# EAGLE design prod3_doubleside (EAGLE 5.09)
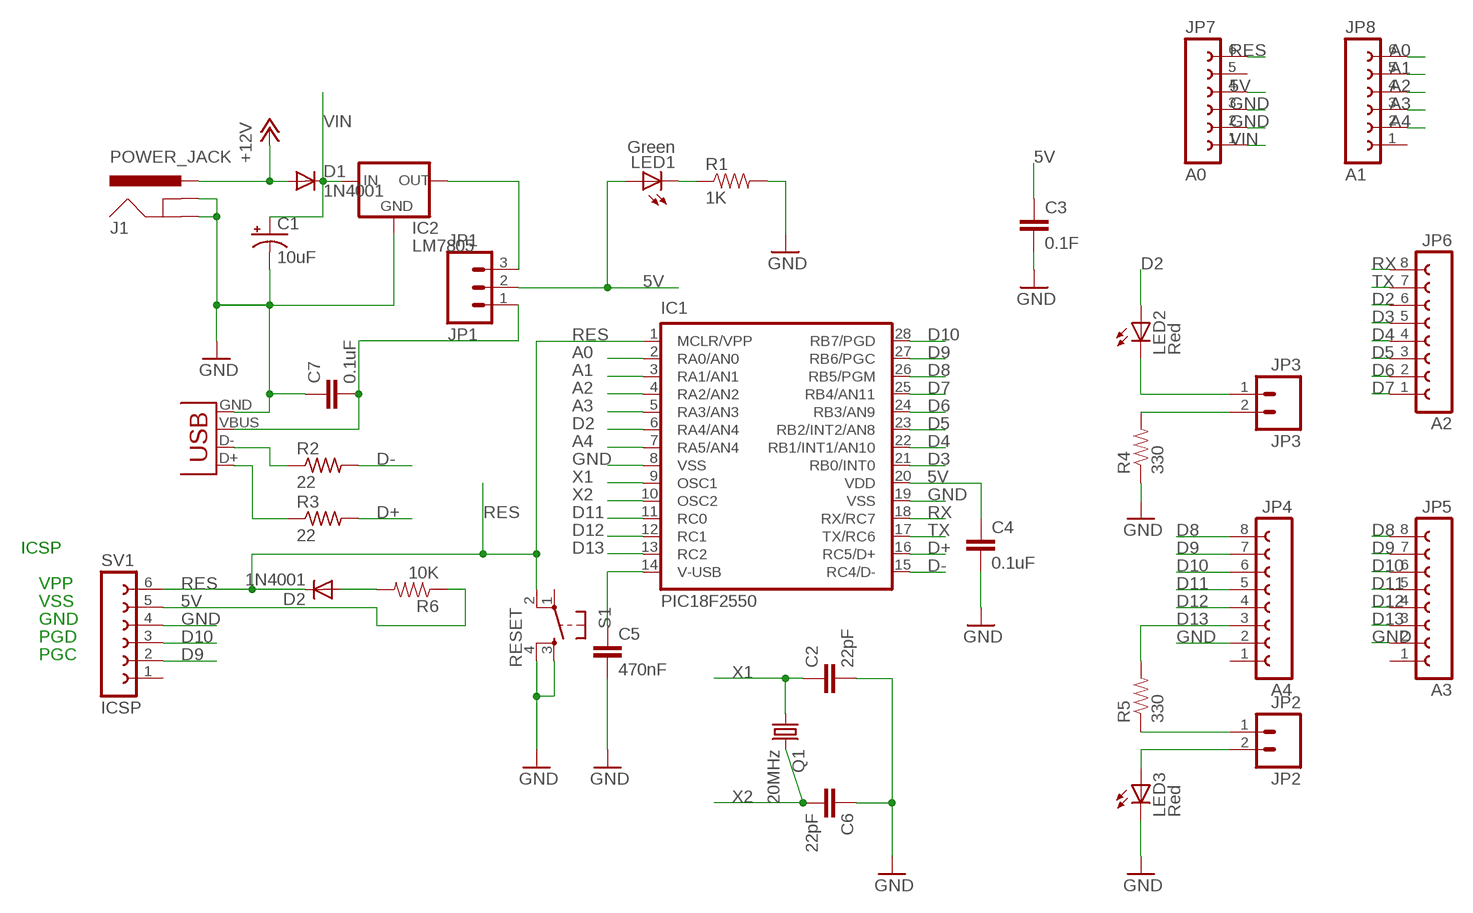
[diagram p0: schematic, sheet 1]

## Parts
C1  10uF  CAP_POLPTH2  [CPOL-RADIAL-10UF-25V]
C2  22pF  CAPPTH  [CAP-PTH-SMALL]
C3  0.1F  CAPPTH1  [CAP-PTH-5MM]
C4  0.1uF  CAPPTH  [CAP-PTH-SMALL]
C5  470nF  CAPPTH1  [CAP-PTH-5MM]
C6  22pF  CAPPTH  [CAP-PTH-SMALL]
C7  0.1uF  CAPPTH  [CAP-PTH-SMALL]
D1  1N4001  DIODEPTH  [DIODE-1N4001]
D2  1N4001  DIODEPTH  [DIODE-1N4001]
IC1  PIC18F2550  [DIL28-3]
IC2  LM7805  V_REG_78XXSIDE  [78XXL]
J1  POWER_JACK  POWER_JACKPTH  [POWER_JACK_PTH]
JP1  JP1  M03PTH  [1X03]
JP2  JP2  M02PTH  [1X02]
JP3  JP3  M02PTH  [1X02]
JP4  A4  FE08-1  [FE08]
JP5  A3  FE08-1  [FE08]
JP6  A2  FE08-1  [FE08]
JP7  A0  FE06-1  [FE06]
JP8  A1  FE06-1  [FE06]
LED1  Green  LED3MM  [LED3MM]
LED2  Red  LED3MM  [LED3MM]
LED3  Red  LED3MM  [LED3MM]
Q1  20MHz  CRYSTALHC49US  [HC49US]
R1  1K  RESISTORPTH1  [AXIAL-0.3]
R2  22  R-US_0207/15  [0207/15]
R3  22  R-US_0207/15  [0207/15]
R4  330  RESISTORPTH1  [AXIAL-0.3]
R5  330  RESISTORPTH1  [AXIAL-0.3]
R6  10K  RESISTORPTH1  [AXIAL-0.3]
S1  RESET  TAC_SWITCHPTH  [TACTILE-PTH]
SV1  ICSP  FE06-1  [FE06]
X1  USBPTH  [USB-B-PTH]

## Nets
5V: C3.1 C4.1 IC1.20(VDD) JP1.2 JP7.4 LED1.A R6.P$1 SV1.5
+12V: D1.A J1.PWR
A0: IC1.2(RA0/AN0) JP8.6
A1: IC1.3(RA1/AN1) JP8.5
A2: IC1.4(RA2/AN2) JP8.4
A3: IC1.5(RA3/AN3) JP8.3
A4: IC1.7(RA5/AN4) JP8.2
D2: IC1.6(RA4/AN4) JP6.6 LED2.A
D3: IC1.21(RB0/INT0) JP6.5
D4: IC1.22(RB1/INT1/AN10) JP6.4
D5: IC1.23(RB2/INT2/AN8) JP6.3
D6: IC1.24(RB3/AN9) JP6.2
D7: IC1.25(RB4/AN11) JP6.1
D8: IC1.26(RB5/PGM) JP4.8 JP5.8
D9: IC1.27(RB6/PGC) JP4.7 JP5.7 SV1.2
D10: IC1.28(RB7/PGD) JP4.6 JP5.6 SV1.3
D11: IC1.11(RC0) JP4.5 JP5.5
D12: IC1.12(RC1) JP4.4 JP5.4
D13: IC1.13(RC2) JP4.3 JP5.3 R5.P$2
D+: IC1.16(RC5/D+) R3.2
D-: IC1.15(RC4/D-) R2.2
GND: C1.2(-) C2.2 C3.2 C4.2 C5.2 C6.1 C7.1 IC1.8(VSS) IC1.19(VSS) IC2.GND J1.GND J1.GNDBREAK JP4.2 JP5.2 JP7.2 JP7.3 LED3.K(C) R1.P$2 R4.P$1 S1.3 S1.4 SV1.4 X1.GND
N$1: D2.A R6.P$2
N$2: LED1.K(C) R1.P$1
N$3: JP3.2 R4.P$2
N$4: C7.2 JP1.1 X1.VBUS
N$5: R2.1 X1.D-
N$6: R3.1 X1.D+
N$7: JP3.1 LED2.K(C)
N$8: JP2.1 R5.P$1
N$10: JP2.2 LED3.A
N$11: IC2.OUT JP1.3
N$15: C5.1 IC1.14(V-USB)
RES: D2.C IC1.1(MCLR/VPP) JP7.6 S1.2 SV1.6
RX: IC1.18(RX/RC7) JP6.8
TX: IC1.17(TX/RC6) JP6.7
VIN: C1.1(+) D1.C IC2.IN JP7.1
X1: C2.1 IC1.9(OSC1) Q1.1
X2: C6.2 IC1.10(OSC2) Q1.2
Unconnected: JP4.1 JP5.1 JP7.5 JP8.1 S1.1 SV1.1

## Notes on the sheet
- ICSP
- VPP
- VSS
- GND
- PGD
- PGC

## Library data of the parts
C1 = SparkFun:CAP_POL: Capacitor Polarized
C2-C7 = SparkFun:CAP: Capacitor
D1 D2 = SparkFun:DIODE: Diode
IC1 = SparkFun:PIC18F2550
IC2 = SparkFun:V_REG_78XX: Voltage Regulator Standard 7805 5V regulator. IGO (Input Ground Output). Spark Fun Electronics SKU : COM-00107
J1 = SparkFun:POWER_JACK: Power Jack This is the standard 5.5mm barrel jack for power. The PTH is the most common, proven, reliable, footprint. All others are experimental. The Slot footprint only works if the mill layer is transmitted to the PCB fab house so be warned. Spark Fun Electronics SKU : PRT-00119. Mating wall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
JP1 = SparkFun:M03: Header 3 Standard 3-pin 0.1" header. Use with straight break away headers (SKU : PRT-00116), right angle break away headers (PRT-00553), swiss pins (PRT-00743), machine pins (PRT-00117), and female headers (PRT-00115). Molex polarized connector foot print use with SKU : PRT-08232 with associated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
JP2 JP3 = SparkFun:M02: Header 2
JP4-JP6 = con-lsta:FE08-1: FEMALE HEADER
JP7 JP8 SV1 = con-lsta:FE06-1: FEMALE HEADER
LED1-LED3 = SparkFun:LED: LEDs
Q1 = SparkFun:CRYSTAL: Crystals
R1 R4-R6 = SparkFun:RESISTOR: Resistor
R2 R3 = rcl:R-US_: RESISTOR, American symbol
S1 = SparkFun:TAC_SWITCH: Momentary Switch Button commonly used for reset or general input. Spark Fun Electronics SKU : COM-00097
X1 = SparkFun:USB: USB Connectors USB-B-PTH is fully proven SKU : PRT-00139 USB-miniB is fully proven SKU : PRT-00587 USB-A-PCB is untested. USB-A-H is throughly reviewed, but untested. Spark Fun Electronics SKU : PRT-00437 USB-B-SMT is throughly reviewed, but untested. Needs silkscreen touching up. USB-A-S has not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

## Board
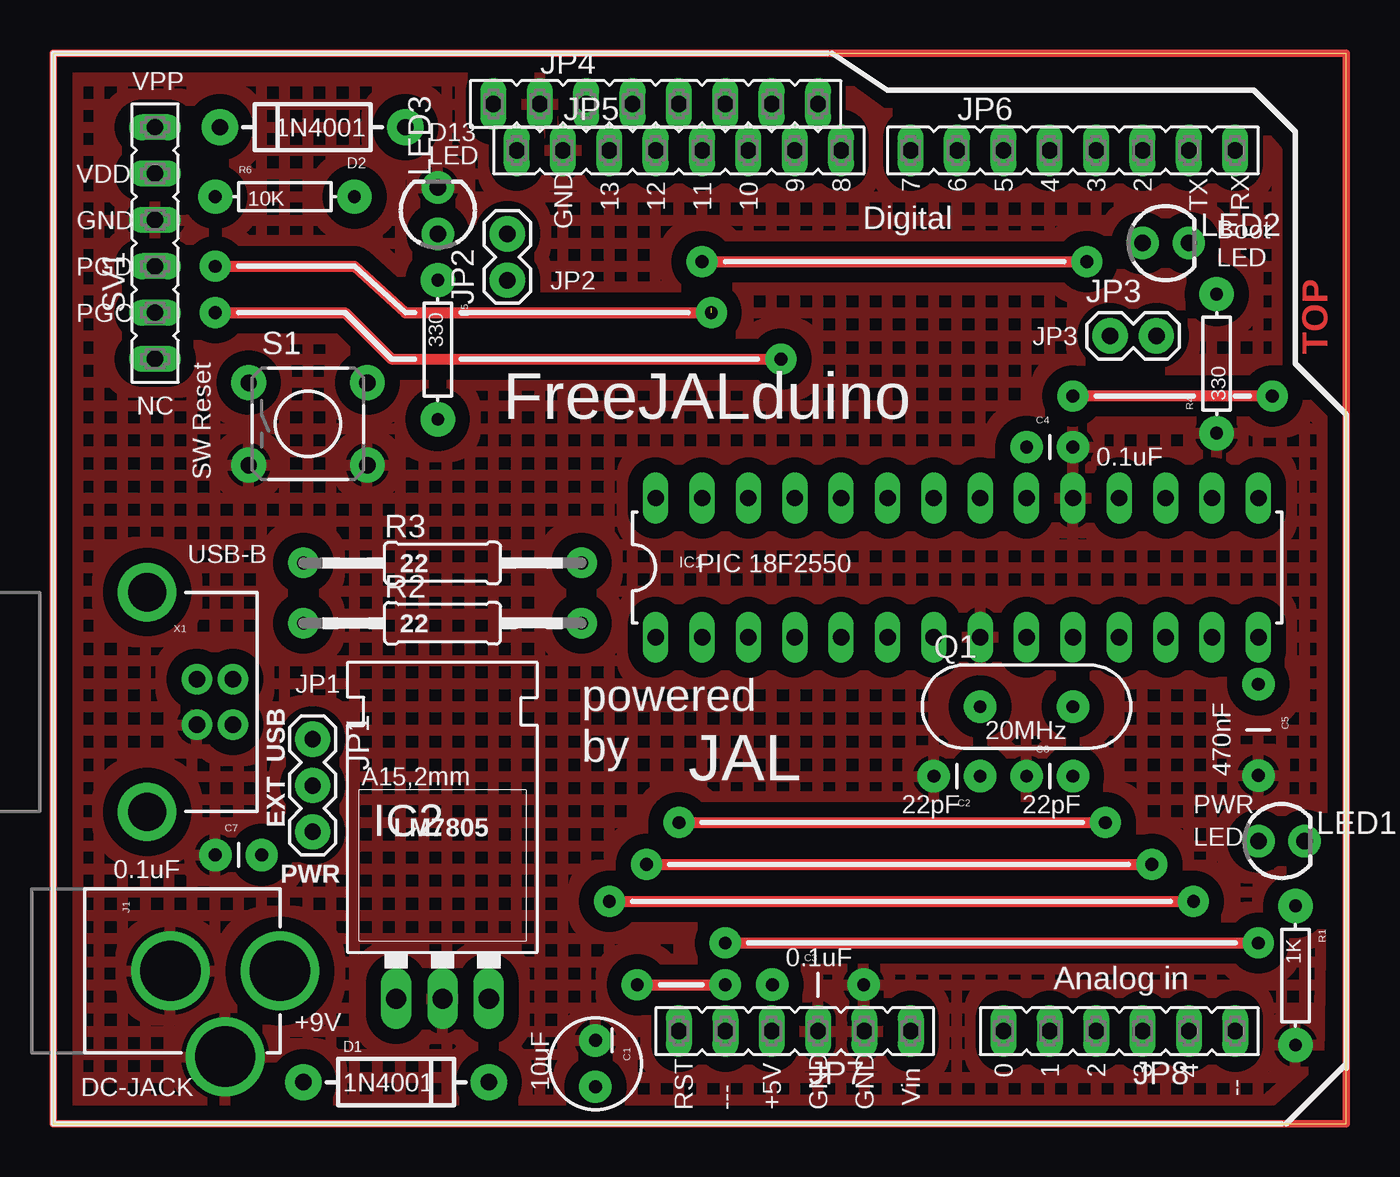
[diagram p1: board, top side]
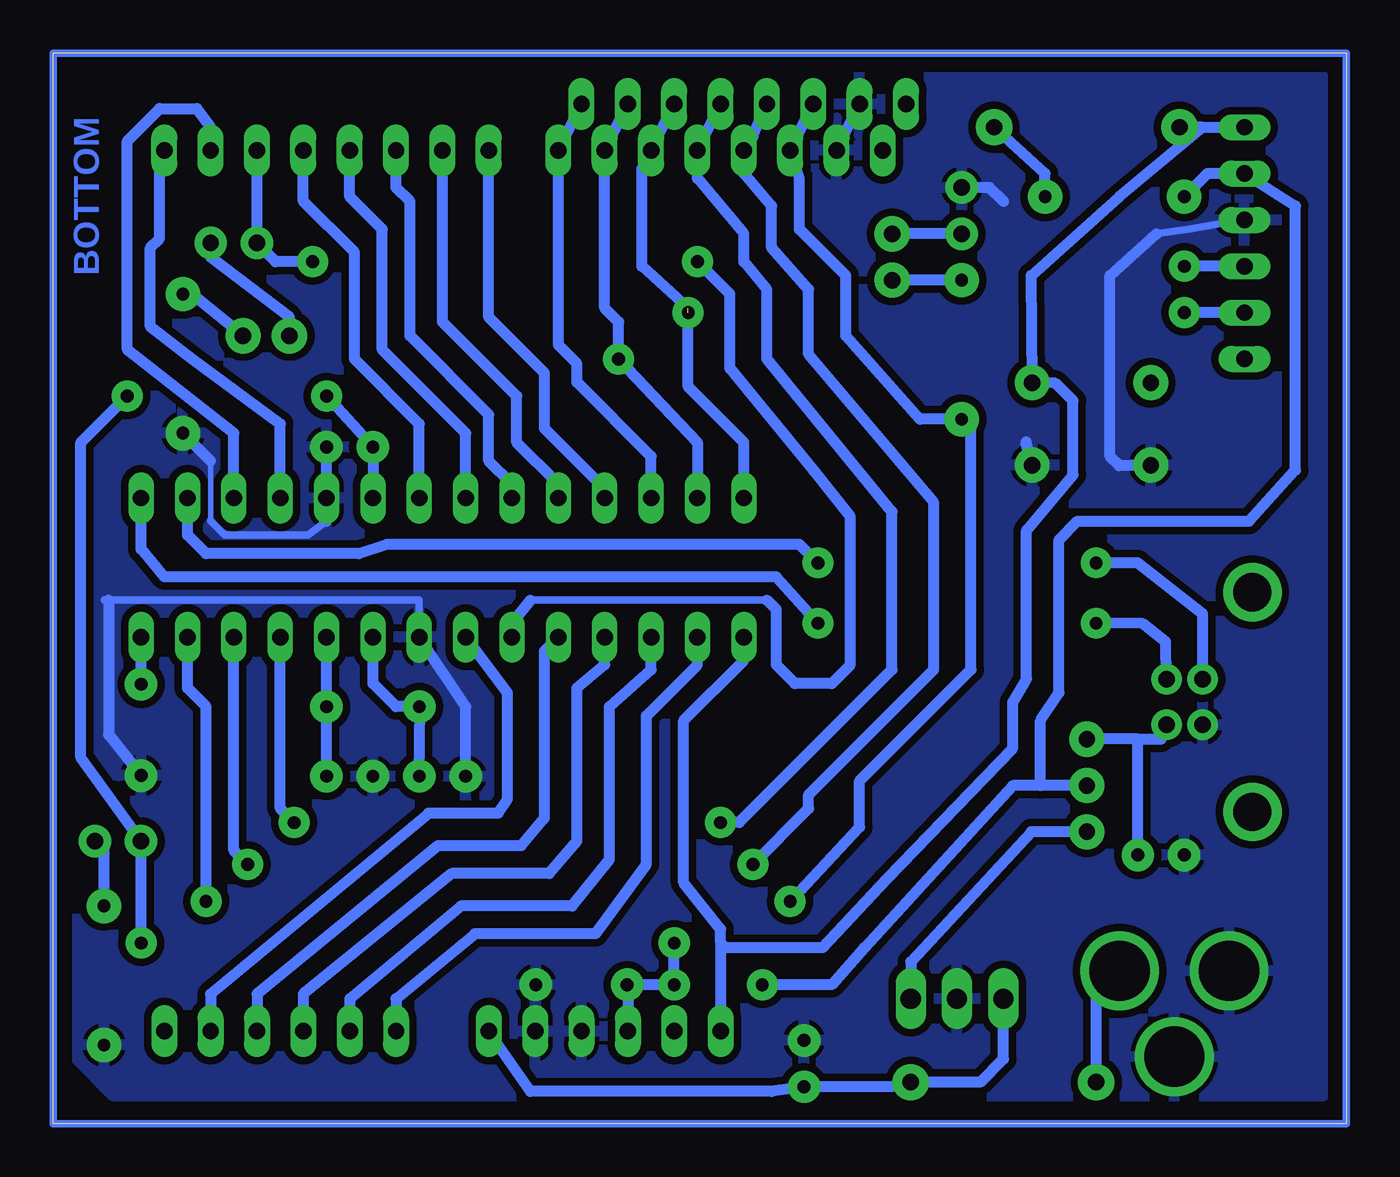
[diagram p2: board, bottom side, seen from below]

Size 70.87 x 58.67 mm. Coordinates in mm from the lower left corner, seen from the top.
Outline: 0,0 70.87,0 70.87,58.67 0,58.67 0,0
Copper layers (1*16): Top 0.035mm / dielectric 1.5mm / Bottom 0.035mm
Design rules "10mils": minimum track width 10mil, minimum drill 24mil, track to track 10mil, track to pad 10mil, pad to pad 10mil, via to via 10mil, smd to smd 10mil, copper to edge 40mil, drill to drill 10mil, minimum pad ring 10mil, minimum via ring 8mil, stop-mask expansion 0mil, vias tented up to drill 0mil, thermal gap 10mil

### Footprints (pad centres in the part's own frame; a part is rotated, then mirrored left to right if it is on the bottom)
CPOL-RADIAL-10UF-25V = drill 0.7 pad 1.778 round: 1 1.27,0; 2 -1.27,0
CAP-PTH-SMALL = drill 0.7 pad 1.778 round: 1 0,0; 2 2.54,0
CAP-PTH-5MM = drill 0.7 pad 1.778 round: 1 -2.5,0; 2 2.5,0
DIODE-1N4001 = drill 0.9 pad 1.981 round: A -5.08,0; C 5.08,0
DIL28-3 = drill 0.9 pad 1.27 long: 1 -16.51,-3.81; 2 -13.97,-3.81; 3 -11.43,-3.81; 4 -8.89,-3.81; 5 -6.35,-3.81; 6 -3.81,-3.81; 7 -1.27,-3.81; 8 1.27,-3.81; 9 3.81,-3.81; 10 6.35,-3.81; 11 8.89,-3.81; 12 11.43,-3.81; 13 13.97,-3.81; 14 16.51,-3.81; 15 16.51,3.81; 16 13.97,3.81; 17 11.43,3.81; 18 8.89,3.81; 19 6.35,3.81; 20 3.81,3.81; 21 1.27,3.81; 22 -1.27,3.81; 23 -3.81,3.81; 24 -6.35,3.81; 25 -8.89,3.81; 26 -11.43,3.81; 27 -13.97,3.81; 28 -16.51,3.81
78XXL = drill 1.1 pad 1.676 long: GND 0,-3.81; IN -2.54,-3.81; OUT 2.54,-3.81
POWER_JACK_PTH = drill 3.3 pad 4 round: GND 0,7.7; GNDBREAK 4.7,10.7; PWR 0,13.7
1X03 = drill 0.9 pad 1.93 round: 1 0,0; 2 2.54,0; 3 5.08,0
1X02 = drill 0.9 pad 1.93 round: 1 0,0; 2 2.54,0
FE08 = drill 0.9 pad 1.422 long: 1 -8.89,0; 2 -6.35,0; 3 -3.81,0; 4 -1.27,0; 5 1.27,0; 6 3.81,0; 7 6.35,0; 8 8.89,0
FE06 = drill 0.9 pad 1.422 long: 1 -6.35,0; 2 -3.81,0; 3 -1.27,0; 4 1.27,0; 5 3.81,0; 6 6.35,0
LED3MM = drill 0.9 pad 1.778 round: A -1.27,0; K 1.27,0
HC49US = drill 0.7 pad 1.778 round: 1 -2.54,0; 2 2.54,0
AXIAL-0.3 = drill 0.7 pad 1.88 round: P$1 -3.81,0; P$2 3.81,0
0207/15 = drill 0.7 pad 1.676 round: 1 -7.62,0; 2 7.62,0
TACTILE-PTH = drill 0.9 pad 1.9 round: 1 -3.251,2.261; 2 3.251,2.261; 3 -3.251,-2.261; 4 3.251,-2.261
USB-B-PTH = drill 0.9 pad 1.676 round: D+ 0,1.25; D- 1.981,1.25; GND 0,-1.25; VBUS 1.981,-1.25 | drill 2.1 pad 3.2 round: P$1 -2.718,-6.02; P$2 -2.718,6.02

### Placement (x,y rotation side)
C1  29.72,3.3 270 top
C2  50.8,19.05 180 top
C3  41.91,7.62 0 top
C4  53.34,37.08 0 top
C5  66.04,21.59 270 top
C6  53.34,19.05 0 top
C7  8.89,14.73 0 top
D1  18.8,2.29 0 top
D2  14.22,54.61 180 top
IC1  49.53,30.48 0 top
IC2  21.34,10.67 0 top
J1  -1.27,8.38 270 top
JP1  14.22,21.08 270 top
JP2  24.89,46.23 90 top
JP3  57.91,43.18 0 top
JP4  33.02,55.88 0 top
JP5  34.29,53.34 0 top
JP6  55.88,53.34 0 top
JP7  40.64,5.08 180 top
JP8  58.42,5.08 180 top
LED1  67.31,15.49 0 top
LED2  60.96,48.26 0 top
LED3  21.08,50.04 90 top
Q1  53.34,22.86 0 top
R1  68.07,8.13 270 top
R2  21.34,27.43 0 top
R3  21.34,30.73 0 top
R4  63.75,41.66 90 top
R5  21.08,42.42 270 top
R6  12.7,50.8 0 top
S1  13.97,38.35 0 top
SV1  5.59,48.26 90 top
X1  7.87,23.11 0 top

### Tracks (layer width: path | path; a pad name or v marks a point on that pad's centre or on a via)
5V  (via drill 0.7 pad 1.7)
  Top 0.61: C3.1 39.62,7.62 | v32,7.62 v36.83,7.62 | v36.83,9.91 v66.04,9.91 | v66.8,39.88 v55.88,39.88
  Bottom 0.61: R6.P$1 7.62,52.07 SV1.5 2.79,50.29 2.79,35.81 5.33,33.02 14.73,33.02 15.75,32 15.75,23.62 16.76,22.1 16.76,18.54 | IC1.20 C4.1 v55.88,39.88 | JP7.4 39.37,7.58 C3.1 v36.83,7.62 v36.83,9.91 | JP1.2 16.76,18.54 | 16.76,18.54 18.29,18.54 26.42,9.65 28.19,7.62 v32,7.62 | v66.04,9.91 LED1.A 69.34,20.07 69.34,37.34 v66.8,39.88
+12V
  Bottom 0.61: J1.PWR 12.43,8.4 13.72,7.11 D1.A
A0
  Bottom 0.61: IC1.2 35.56,25.15 38.35,22.35 38.35,14.22 41.15,10.41 47.75,10.41 52.07,6.86 JP8.6
A1
  Bottom 0.61: IC1.3 38.1,24.89 40.39,22.86 40.39,14.48 42.42,11.94 48.51,11.94 54.61,6.86 JP8.5
A2
  Bottom 0.61: IC1.4 40.64,25.15 42.16,23.88 42.16,15.49 43.69,13.72 49.02,13.72 57.15,7.11 JP8.4
A3
  Bottom 0.61: JP8.3 59.69,7.11 49.78,15.24 45.21,15.24 43.94,16.76 43.94,25.91 IC1.5
A4
  Bottom 0.61: IC1.7 45.97,23.62 45.97,17.78 46.48,17.02 50.29,17.02 62.23,7.11 JP8.2
D2  (via drill 0.7 pad 1.7)
  Top 0.61: v35.56,47.24 v56.64,47.24
  Bottom 0.406: 31.75,28.7 44.7,28.7
  Bottom 0.61: IC1.6 45.72,27.43 44.7,28.7 | 31.75,28.7 31.24,28.19 31.24,25.15 30.23,24.13 28.19,24.13 27.18,25.15 27.18,33.27 29.21,35.81 33.78,41.4 33.78,45.47 v35.56,47.24 | JP6.6 LED2.A 58.67,47.24 v56.64,47.24
D3
  Bottom 0.61: IC1.21 50.8,38.35 54.36,41.91 54.36,47.75 57.15,50.55 JP6.5
D4
  Bottom 0.61: IC1.22 48.26,37.85 52.83,42.42 52.83,49.02 54.61,50.8 JP6.4
D5
  Bottom 0.61: IC1.23 45.72,35.05 46.99,36.32 46.99,38.86 51.31,43.18 51.31,50.55 52.07,51.31 JP6.3
D6
  Bottom 0.61: IC1.24 43.18,35.05 45.47,37.34 45.47,39.88 49.53,43.94 JP6.2
D7
  Bottom 0.61: IC1.25 40.64,34.8 43.94,38.1 43.94,41.15 46.99,44.2 JP6.1
D8
  Bottom 0.61: IC1.26 38.1,36.58 42.16,40.64 42.16,41.66 43.18,42.67 JP5.8 JP4.8
D9  (via drill 0.7 pad 1.7)
  Top 0.61: v8.89,44.45 16,44.45 18.54,41.91 v39.88,41.91
  Bottom 0.61: IC1.27 35.56,37.34 v39.88,41.91 39.88,43.94 40.64,44.7 JP5.7 JP4.7 | SV1.2 v8.89,44.45
D10  (via drill 0.7 pad 1.7)  (1 unrouted)
  Top 0.61: v8.89,46.99 16.51,46.99 19.3,44.45 v36.07,44.45
  Bottom 0.61: IC1.28 33.02,37.34 36.07,40.39 36.07,44.7 38.61,46.99 38.61,52.32 JP5.6 JP4.6 | SV1.3 v8.89,46.99
D11  (via drill 0.7 pad 1.7)
  Top 0.61: v34.29,16.51 v57.66,16.51
  Bottom 0.61: IC1.11 58.42,17.27 v57.66,16.51 | v34.29,16.51 33.27,16.51 24.89,24.89 24.89,33.53 31.75,41.91 31.75,45.72 33.02,47.24 33.02,48.77 35.56,51.82 JP5.5 JP4.5
D12  (via drill 0.7 pad 1.7)
  Top 0.61: v32.51,14.22 v60.2,14.22
  Bottom 0.61: 32.63,53.93 JP5.4 33.02,52.07 31.5,50.29 31.5,48.01 29.46,45.72 29.46,42.16 22.61,34.04 22.61,24.89 29.46,18.03 29.46,17.27 v32.51,14.22 | 32.63,53.93 32.51,54.1 | IC1.12 60.96,14.99 v60.2,14.22 | 32.63,53.93 JP4.4
D13  (via drill 0.7 pad 1.7)
  Top 0.61: v30.48,12.19 v62.48,12.19
  Bottom 0.61: IC1.13 63.5,23.88 62.48,22.86 v62.48,12.19 | v30.48,12.19 29.97,12.7 26.67,16.26 26.67,18.8 20.57,24.89 20.57,38.1 R5.P$2 | R5.P$2 21.2,38.7 21.2,38.61 | 21.2,38.61 23.37,38.61 27.43,43.18 27.43,46.48 29.97,49.02 29.97,51.82 JP5.3 JP4.3 | R5.P$2 21.2,38.61
D+
  Bottom 0.61: IC1.16 63.5,32.26 62.48,31.24 54.1,31.24 52.58,31.75 29.97,31.75 R3.2
D-
  Bottom 0.61: R2.2 31.24,29.97 64.77,29.97 66.04,31.5 IC1.15
GND
  Bottom 0.305: 62.23,33.02 62.23,36.32
  Bottom 0.406: 55.88,33.02 56.9,32.26 61.47,32.26 62.23,33.02 | IC1.8 50.8,28.7 67.82,28.7 68.07,28.7 | 5.84,49.53 8.64,49.02 10.41,48.77
  Bottom 0.61: 55.88,33.02 IC1.19 C4.2 | JP7.2 44.41,5.08 | JP5.2 JP4.2 | 18.8,50.55 19.56,51.31 LED3.K 21.59,51.05 | IC2.GND 21.34,8.13 | 66.04,19.05 C5.2 67.82,21.34 67.82,28.7 | C2.2 48.26,22.86 IC1.8 | S1.4 17.55,37.36 | 5.84,49.53 SV1.4 | 10.41,48.77 12.95,46.48 12.95,36.58 12.45,36.07 10.67,36.07 | 62.23,36.32 R4.P$1
  pour Top (isolate 0.813, hatched): 1.27,57.4 42.67,57.4 45.47,55.37 65.28,55.37 67.06,53.34 67.06,41.15 69.85,38.35 69.34,3.56 66.8,1.27 1.02,1.02
  pour Bottom (isolate 0.406, hatched): 1.27,57.4 1.27,1.52 67.56,1.52 69.6,3.56 69.6,38.1 69.85,38.35 67.06,41.15 67.06,53.34 66.8,53.34 65.02,55.12 44.2,55.12 41.91,57.4
N$1
  Bottom 0.61: R6.P$2 16.51,52.07 D2.A
N$2
  Bottom 0.61: R1.P$1 68.07,15.24 LED1.K
N$3
  Bottom 0.61: R4.P$2 63.25,45.47 JP3.2
N$4
  Bottom 0.61: 9.91,21.66 X1.VBUS 10.16,21.08 11.43,21.08 | 11.43,21.08 JP1.1 | C7.2 11.43,21.08
N$5
  Bottom 0.61: X1.D- 9.91,26.42 11.16,27.41 R2.1
N$6
  Bottom 0.61: X1.D+ 7.87,27.94 11.43,30.73 R3.1
N$7
  Bottom 0.61: LED2.K 62.23,47.5 57.91,44.2 JP3.1
N$8
  Bottom 0.61: R5.P$1 JP2.1
N$9
  Top 0.406: 0,0 0,58.67 70.87,58.67 70.87,0 0,0
N$10
  Bottom 0.61: LED3.A JP2.2
N$11
  Bottom 0.61: IC2.OUT 23.88,8.89 17.27,16 JP1.3
N$12
  Bottom 0.406: 0,58.67 70.87,58.67 70.87,0 0,0 0,58.67
N$15
  Bottom 0.61: C5.1 IC1.14
RES
  Bottom 0.61: IC1.1 33.02,25.4 36.32,22.1 36.32,13.21 34.29,10.67 34.29,9.91 | 34.29,9.91 JP7.6 | SV1.6 D2.C 7.87,54.61 12.45,50.8 17.27,46.48 S1.2 15.95,40.59 14.99,39.62 14.99,35.56 17.53,32.51 17.53,24.38 18.29,23.11 18.29,20.57 25.15,13.46 28.7,9.65 34.04,9.65 34.29,9.91
RX
  Bottom 0.61: IC1.18 58.42,38.35 63.25,41.91 65.53,43.69 65.53,48.01 65.02,48.51 65.02,53.09 JP6.8
TX
  Bottom 0.61: IC1.17 60.96,37.85 66.8,42.42 66.8,53.85 65.02,55.63 62.99,55.63 62.23,54.61 JP6.7
VIN
  Bottom 0.61: IC2.IN 18.8,3.56 20.07,2.29 D1.C 24.89,2.03 C1.1 31.5,1.78 44.7,1.78 JP7.1
X1
  Bottom 0.61: IC1.9 53.34,24.13 52.07,22.86 Q1.1 50.76,22.82 C2.1
X2
  Bottom 0.61: C6.2 Q1.2 IC1.10

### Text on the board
Top: TOP
Bottom: BOTTOM
tPlace: VPP | D13 | LED | VDD | 9 | 8 | 7 | 6 | 5 | 4 | 3 | 2 | 13 | 12 | 11 | 10 | Digital | TX | RX | GND | GND | Boot | JP2 | LED | PGD | PGC | JP3 | NC | FreeJALduino | 0.1uF | SW Reset | USB-B | 22 | PIC 18F2550 | 22 | JP1 | powered | 20MHz | USB | by | JAL | 470nF | LM7805 | 22pF | 22pF | PWR | EXT | LED | PWR | 0.1uF | 0.1uF | Analog in | +9V | 10uF | 0 | 1 | 2 | 3 | 4 | DC-JACK | -- | RST | --- | +5V | GND | GND | Vin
